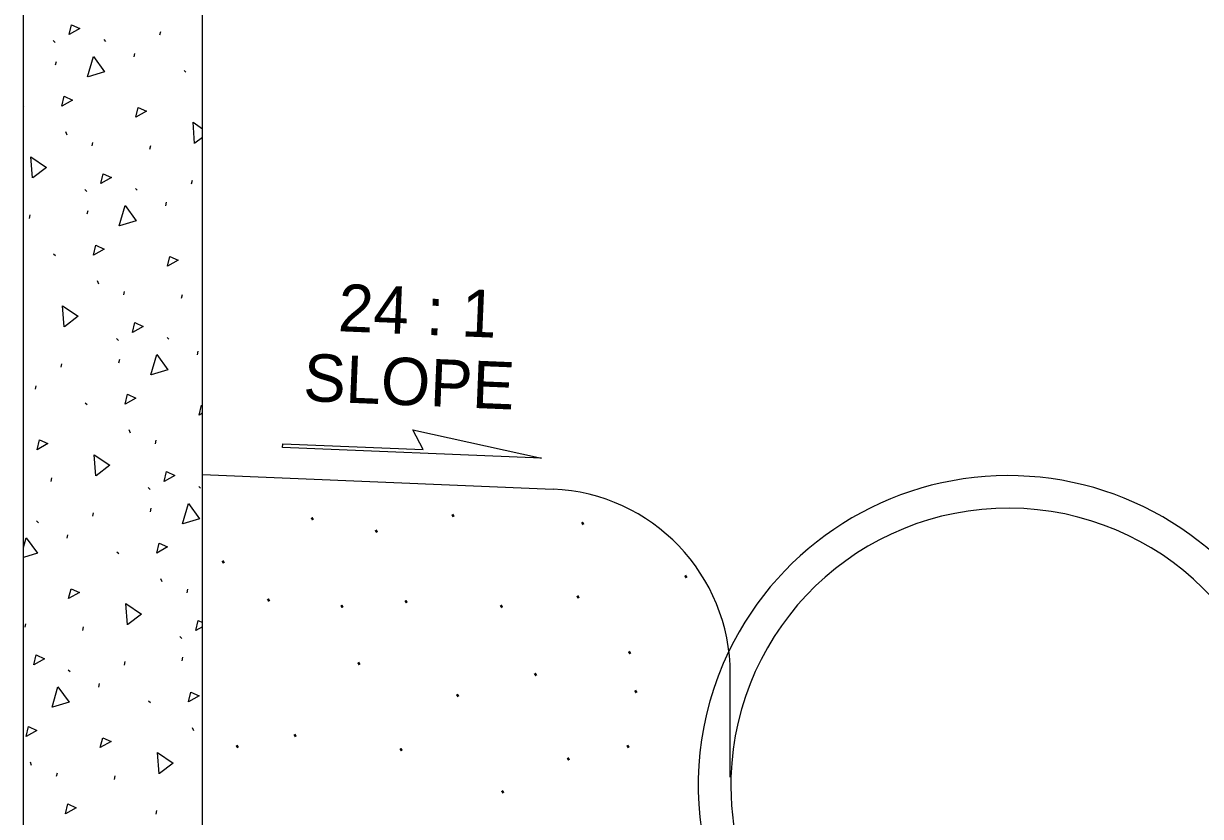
# Model space of a CAD drawing. Extents: x 99862 to 103151, y 100000 to 102076.
# Drawn here: x 100604.1 to 101001.8, y 100755.3 to 101023.2 of the extents above; entities that cross this region are included whole.
import ezdxf

# ---------------------------------------------------------------- set-up
doc = ezdxf.new("R2010")
doc.units = 0
for name, color, linetype in [('Level 1', 7, 'Continuous'), ('Level 16', 7, 'Continuous'), ('Level 17', 7, 'Continuous'), ('Level 20', 7, 'Continuous'), ('Level 3', 7, 'Continuous')]:
    doc.layers.add(name, color=color, linetype=linetype)

msp = doc.modelspace()

# ---------------------------------------------------------------- linework, layer by layer
at = {"layer": 'Level 1'}
msp.add_arc((100936.81, 100765.78), 104.72, 154.3283, 26.0354, dxfattribs=at)
at = {"layer": 'Level 16'}
for p, q in [((100650.21, 101019.41), (100650.47, 101020.61)), ((100614.16, 101017.47), (100614.8, 101016.84)), ((100631.2, 101017.85), (100631.84, 101017.23)), ((100641.5, 101011.98), (100641.75, 101013.17)), ((100614.94, 101009.26), (100615.2, 101010.46)), ((100658.35, 101007.42), (100658.99, 101006.8)), ((100604.12, 100995.25), (100604.21, 100995.16)), ((100618.35, 100986.73), (100618.7, 100985.66)), ((100627.3, 100981.89), (100627.55, 100983.09)), ((100646.84, 100980.83), (100647.1, 100982.03)), ((100641.9, 100967.52), (100642.54, 100966.9)), ((100660.91, 100969.08), (100661.16, 100970.28)), ((100624.86, 100967.14), (100625.5, 100966.51)), ((100625.64, 100958.93), (100625.9, 100960.13)), ((100652.19, 100961.65), (100652.45, 100962.85)), ((100606.13, 100957.43), (100606.39, 100958.63)), ((100614.27, 100945.45), (100614.91, 100944.83)), ((100629.04, 100936.4), (100629.4, 100935.33)), ((100638, 100931.56), (100638.25, 100932.76)), ((100657.54, 100930.5), (100657.8, 100931.7)), ((100635.56, 100916.81), (100636.2, 100916.19)), ((100652.6, 100917.2), (100653.24, 100916.57)), ((100662.89, 100911.32), (100663.14, 100912.52)), ((100616.83, 100907.11), (100617.08, 100908.31)), ((100636.34, 100908.6), (100636.6, 100909.8)), ((100608.11, 100899.68), (100608.37, 100900.88)), ((100624.97, 100895.13), (100625.61, 100894.5)), ((100639.74, 100886.08), (100640.1, 100885.01)), ((100648.7, 100881.23), (100648.95, 100882.43)), ((100613.46, 100868.53), (100613.72, 100869.73)), ((100646.26, 100866.48), (100646.9, 100865.86)), ((100663.29, 100866.87), (100663.93, 100866.24)), ((100627.53, 100856.78), (100627.78, 100857.98)), ((100647.04, 100858.27), (100647.29, 100859.47)), ((100608.52, 100855.23), (100609.16, 100854.6)), ((100618.81, 100849.35), (100619.06, 100850.55)), ((100635.67, 100844.8), (100636.31, 100844.17)), ((100650.44, 100835.75), (100650.79, 100834.68)), ((100659.39, 100830.9), (100659.65, 100832.1)), ((100604.62, 100819.26), (100604.87, 100820.46)), ((100624.16, 100818.2), (100624.42, 100819.4)), ((100656.95, 100816.15), (100657.59, 100815.53)), ((100657.73, 100807.95), (100657.99, 100809.14)), ((100619.21, 100804.9), (100619.85, 100804.27)), ((100638.22, 100806.45), (100638.48, 100807.65)), ((100629.51, 100799.02), (100629.76, 100800.22)), ((100646.36, 100794.47), (100647, 100793.85)), ((100661.14, 100785.42), (100661.49, 100784.35)), ((100606.36, 100773.78), (100606.71, 100772.71)), ((100615.31, 100768.93), (100615.57, 100770.13)), ((100634.86, 100767.88), (100635.11, 100769.08)), ((100648.92, 100756.12), (100649.18, 100757.32))]:
    msp.add_line(p, q, dxfattribs=at)
for points in [[(100619.56, 101019.5), (100620.37, 101022.85), (100623.19, 101021.54), (100619.56, 101019.5)], [(100625.78, 101005.21), (100627.74, 101012.1), (100631.51, 101006.93), (100625.9, 101005.23)], [(100617.02, 100995.33), (100617.83, 100998.68), (100620.65, 100997.38), (100617.02, 100995.33)], [(100642.05, 100991.57), (100642.86, 100994.92), (100645.68, 100993.61), (100642.05, 100991.57)], [(100661.9, 100982.72), (100661.39, 100989.87), (100664.59, 100987.72)], [(100664.59, 100984.72), (100662.01, 100982.78)], [(100607.13, 100971.08), (100606.62, 100978.23), (100611.93, 100974.66), (100607.24, 100971.14)], [(100630.26, 100969.17), (100631.07, 100972.52), (100633.89, 100971.22), (100630.26, 100969.17)], [(100636.47, 100954.88), (100638.44, 100961.77), (100642.21, 100956.61), (100636.59, 100954.91)], [(100627.71, 100945.01), (100628.52, 100948.36), (100631.34, 100947.05), (100627.71, 100945.01)], [(100652.74, 100941.24), (100653.56, 100944.59), (100656.37, 100943.28), (100652.74, 100941.24)], [(100617.83, 100920.75), (100617.31, 100927.9), (100622.63, 100924.33), (100617.93, 100920.81)], [(100640.95, 100918.84), (100641.77, 100922.19), (100644.59, 100920.89), (100640.95, 100918.84)], [(100647.17, 100904.55), (100649.14, 100911.45), (100652.9, 100906.28), (100647.29, 100904.58)], [(100638.41, 100894.68), (100639.22, 100898.03), (100642.04, 100896.72), (100638.41, 100894.68)], [(100663.44, 100890.91), (100664.25, 100894.26), (100664.59, 100894.11)], [(100664.59, 100891.56), (100663.44, 100890.91)], [(100608.67, 100879.27), (100609.48, 100882.62), (100612.3, 100881.31), (100608.67, 100879.27)], [(100628.52, 100870.42), (100628.01, 100877.58), (100633.32, 100874), (100628.63, 100870.49)], [(100651.65, 100868.52), (100652.47, 100871.87), (100655.29, 100870.56), (100651.65, 100868.52)], [(100657.87, 100854.22), (100659.83, 100861.12), (100663.6, 100855.95), (100657.99, 100854.25)], [(100604.12, 100846.19), (100605.06, 100849.48), (100608.83, 100844.31), (100604.12, 100842.88)], [(100649.11, 100844.35), (100649.92, 100847.7), (100652.74, 100846.39), (100649.11, 100844.35)], [(100619.36, 100828.94), (100620.18, 100832.29), (100622.99, 100830.99), (100619.36, 100828.94)], [(100639.22, 100820.09), (100638.71, 100827.25), (100644.02, 100823.67), (100639.33, 100820.16)], [(100662.35, 100818.19), (100663.16, 100821.54), (100664.59, 100820.88)], [(100664.59, 100819.45), (100662.35, 100818.19)], [(100607.57, 100806.55), (100608.39, 100809.9), (100611.21, 100808.59), (100607.57, 100806.55)], [(100613.79, 100792.25), (100615.75, 100799.15), (100619.52, 100793.98), (100613.91, 100792.28)], [(100659.81, 100794.02), (100660.62, 100797.37), (100663.44, 100796.07), (100659.81, 100794.02)], [(100605.03, 100782.38), (100605.84, 100785.73), (100608.66, 100784.42), (100605.03, 100782.38)], [(100630.06, 100778.61), (100630.87, 100781.96), (100633.69, 100780.66), (100630.06, 100778.61)], [(100649.92, 100769.77), (100649.41, 100776.92), (100654.72, 100773.35), (100650.03, 100769.83)], [(100618.27, 100756.22), (100619.08, 100759.57), (100621.91, 100758.26), (100618.27, 100756.22)]]:
    msp.add_lwpolyline(points, dxfattribs=at)
at = {"layer": 'Level 17'}
for p, q in [((100604.12, 100643.69), (100604.12, 101611.69)), ((100664.59, 100643.69), (100664.59, 101551.14)), ((100664.59, 100870.85), (100783.03, 100865.92)), ((100842.9, 100768.66), (100842.9, 100803.5))]:
    msp.add_line(p, q, dxfattribs=at)
for centre, radius, start, end in [((100936.81, 100765.78), 104.72, 26.0354, 154.3283), ((100780.42, 100803.5), 62.48, 0, 87.6078), ((100936.81, 100765.78), 93.72, 1.118, 178.2436), ((100936.81, 100765.78), 93.72, 178.2436, 3.5092)]:
    msp.add_arc(centre, radius, start, end, dxfattribs=at)
at = {"layer": 'Level 3'}
msp.add_lwpolyline([(100691.7, 100881.3), (100739.14, 100879.32), (100735.68, 100885.95), (100779.07, 100876.42), (100691.64, 100880.06)], close=True, dxfattribs=at)

# ---------------------------------------------------------------- texts
at = {"layer": 'Level 1'}
for p in [(100700.93, 100854.92), (100748.46, 100855.98), (100722.58, 100850.7), (100792.29, 100853.34), (100670.83, 100840.32), (100827.14, 100835.37), (100686.15, 100827.44), (100732.62, 100826.92), (100790.7, 100828.5), (100710.96, 100825.32), (100764.83, 100825.32), (100808.14, 100809.69), (100716.68, 100805.99), (100776.35, 100802.29), (100750.04, 100795.21), (100810.24, 100796.53), (100695.12, 100781.68), (100675.59, 100777.96), (100730.94, 100776.91), (100807.6, 100777.98), (100787.44, 100773.75), (100765.26, 100762.65)]:
    msp.add_text('.', height=6.3, rotation=30.9638, dxfattribs=at).set_placement(p)
at = {"layer": 'Level 20'}
for s, p in [('24 : 1', (100710.21, 100919.31)), ('SLOPE', (100698.44, 100895.77))]:
    msp.add_text(s, height=16, rotation=357.62, dxfattribs=at).set_placement(p)

doc.saveas('drawing.dxf')
